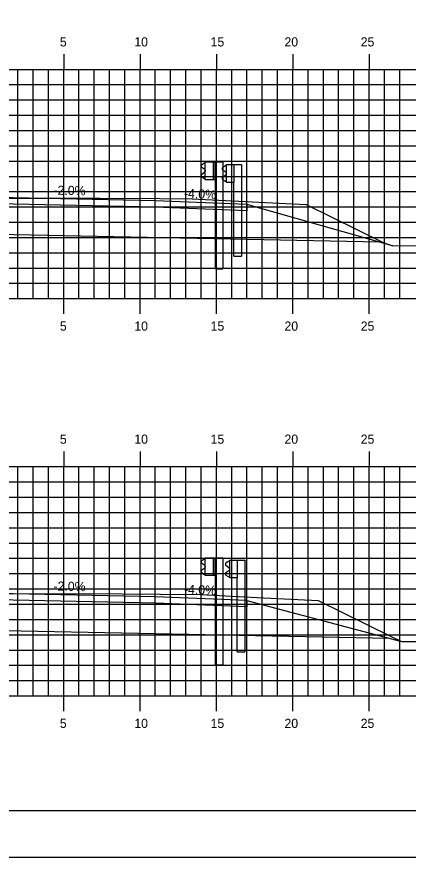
# Model space of a CAD drawing. Extents: x 2194004 to 2194525, y 863888 to 863998.
# Drawn here: x 2194256.9 to 2194282.5, y 863888.4 to 863943.4 of the extents above; entities that cross this region are included whole.
import ezdxf

# ---------------------------------------------------------------- set-up
doc = ezdxf.new("R2010")
doc.units = 0
for name, color, linetype in [('ANNOTATION', 7, 'Continuous'), ('BORDER', 7, 'Continuous'), ('D_Guardrail_Beam_Lt', 7, 'Continuous'), ('H_V ANNOTATION', 7, 'Continuous'), ('MAJOR', 7, 'Continuous'), ('MINOR', 7, 'Continuous'), ('PLOT BOUNDARY', 7, 'Continuous'), ('S_Guardrail_Beam', 7, 'Continuous'), ('S_Roadway_Centerline', 7, 'Continuous'), ('TEMPLATE', 7, 'Continuous')]:
    doc.layers.add(name, color=color, linetype=linetype)

msp = doc.modelspace()

# ---------------------------------------------------------------- linework, layer by layer
at = {"layer": 'BORDER'}
msp.add_lwpolyline([(2194179.986, 863891.446), (2194339.986, 863891.446), (2194339.986, 863996.446), (2194179.986, 863996.446)], close=True, dxfattribs=at)
at = {"layer": 'D_Guardrail_Beam_Lt'}
for p, q in [((2194269.167, 863933.788), (2194269.024, 863933.688)), ((2194269.024, 863933.545), (2194269.219, 863933.409)), ((2194269.257, 863933.809), (2194269.183, 863933.795)), ((2194269.257, 863933.892), (2194269.945, 863933.892)), ((2194269.257, 863932.726), (2194269.257, 863933.892)), ((2194269.778, 863933.892), (2194269.778, 863932.726)), ((2194269.882, 863933.892), (2194269.882, 863932.726)), ((2194269.945, 863933.892), (2194270.415, 863933.892)), ((2194269.945, 863933.892), (2194269.945, 863932.726)), ((2194270.415, 863933.892), (2194270.415, 863926.892)), ((2194269.219, 863933.21), (2194269.024, 863933.073)), ((2194269.024, 863932.93), (2194269.167, 863932.83)), ((2194269.253, 863933.344), (2194269.253, 863933.274)), ((2194269.183, 863932.824), (2194269.257, 863932.809)), ((2194269.945, 863932.726), (2194269.257, 863932.726)), ((2194269.924, 863926.892), (2194269.924, 863932.726)), ((2194269.924, 863926.892), (2194270.415, 863926.892)), ((2194269.167, 863907.878), (2194269.024, 863907.778)), ((2194269.024, 863907.635), (2194269.219, 863907.499)), ((2194269.257, 863907.899), (2194269.183, 863907.885)), ((2194269.257, 863907.982), (2194269.945, 863907.982)), ((2194269.257, 863906.816), (2194269.257, 863907.982)), ((2194269.778, 863907.982), (2194269.778, 863906.816)), ((2194269.882, 863907.982), (2194269.882, 863906.816)), ((2194269.945, 863907.982), (2194270.415, 863907.982)), ((2194269.945, 863907.982), (2194269.945, 863906.816)), ((2194270.415, 863907.982), (2194270.415, 863900.982)), ((2194269.219, 863907.3), (2194269.024, 863907.163)), ((2194269.024, 863907.02), (2194269.167, 863906.92)), ((2194269.253, 863907.434), (2194269.253, 863907.364)), ((2194269.183, 863906.914), (2194269.257, 863906.899)), ((2194269.945, 863906.816), (2194269.257, 863906.816)), ((2194269.924, 863900.982), (2194269.924, 863906.816)), ((2194269.924, 863900.982), (2194270.415, 863900.982))]:
    msp.add_line(p, q, dxfattribs=at)
for centre, major_axis, start_param, end_param in [((2194269.074, 863933.616), (-0.0877, 0), 5.323254, 7.243116), ((2194269.191, 863933.754), (-0.0417, 0), 4.907132, 5.323254), ((2194269.174, 863933.344), (0.0789, 0), 0, 0.959931), ((2194269.074, 863933.002), (-0.0877, 0), 5.323254, 7.243116), ((2194269.174, 863933.274), (0.0789, 0), 5.323254, 6.283185), ((2194269.191, 863932.864), (-0.0417, 0), 0.959931, 1.376053), ((2194269.074, 863907.706), (-0.0877, 0), 5.323254, 7.243116), ((2194269.191, 863907.844), (-0.0417, 0), 4.907132, 5.323254), ((2194269.074, 863907.092), (-0.0877, 0), 5.323254, 7.243116), ((2194269.174, 863907.434), (0.0789, 0), 0, 0.959931), ((2194269.174, 863907.364), (0.0789, 0), 5.323254, 6.283185), ((2194269.191, 863906.954), (-0.0417, 0), 0.959931, 1.376053)]:
    msp.add_ellipse(centre, major_axis=major_axis, ratio=0.995501, start_param=start_param, end_param=end_param, dxfattribs=at)
at = {"layer": 'MAJOR'}
for p, q in [((2194259.986, 863940.948), (2194259.986, 863939.946)), ((2194264.986, 863940.948), (2194264.986, 863939.946)), ((2194269.986, 863940.948), (2194269.986, 863939.946)), ((2194274.986, 863940.948), (2194274.986, 863939.946)), ((2194279.986, 863940.948), (2194279.986, 863939.946)), ((2194184.986, 863939.946), (2194324.986, 863939.946)), ((2194184.986, 863939.946), (2194324.986, 863939.946)), ((2194259.986, 863924.946), (2194259.986, 863939.946)), ((2194264.986, 863924.946), (2194264.986, 863939.946)), ((2194269.986, 863924.946), (2194269.986, 863939.946)), ((2194274.986, 863924.946), (2194274.986, 863939.946)), ((2194279.986, 863924.946), (2194279.986, 863939.946)), ((2194184.986, 863934.946), (2194324.986, 863934.946)), ((2194184.986, 863929.946), (2194324.986, 863929.946)), ((2194184.986, 863924.946), (2194324.986, 863924.946)), ((2194259.986, 863923.944), (2194259.986, 863924.946)), ((2194264.986, 863923.944), (2194264.986, 863924.946)), ((2194269.986, 863923.944), (2194269.986, 863924.946)), ((2194274.986, 863923.944), (2194274.986, 863924.946)), ((2194279.986, 863923.944), (2194279.986, 863924.946)), ((2194259.986, 863914.948), (2194259.986, 863913.946)), ((2194264.986, 863914.948), (2194264.986, 863913.946)), ((2194269.986, 863914.948), (2194269.986, 863913.946)), ((2194274.986, 863914.948), (2194274.986, 863913.946)), ((2194279.986, 863914.948), (2194279.986, 863913.946)), ((2194184.986, 863913.946), (2194324.986, 863913.946)), ((2194184.986, 863913.946), (2194324.986, 863913.946)), ((2194259.986, 863898.946), (2194259.986, 863913.946)), ((2194264.986, 863898.946), (2194264.986, 863913.946)), ((2194269.986, 863898.946), (2194269.986, 863913.946)), ((2194274.986, 863898.946), (2194274.986, 863913.946)), ((2194279.986, 863898.946), (2194279.986, 863913.946)), ((2194184.986, 863908.946), (2194324.986, 863908.946)), ((2194184.986, 863903.946), (2194324.986, 863903.946)), ((2194184.986, 863898.946), (2194324.986, 863898.946)), ((2194259.986, 863897.944), (2194259.986, 863898.946)), ((2194264.986, 863897.944), (2194264.986, 863898.946)), ((2194269.986, 863897.944), (2194269.986, 863898.946)), ((2194274.986, 863897.944), (2194274.986, 863898.946)), ((2194279.986, 863897.944), (2194279.986, 863898.946))]:
    msp.add_line(p, q, dxfattribs=at)
at = {"layer": 'MINOR'}
for p, q in [((2194256.986, 863924.946), (2194256.986, 863939.946)), ((2194257.986, 863924.946), (2194257.986, 863939.946)), ((2194258.986, 863924.946), (2194258.986, 863939.946)), ((2194260.986, 863924.946), (2194260.986, 863939.946)), ((2194261.986, 863924.946), (2194261.986, 863939.946)), ((2194262.986, 863924.946), (2194262.986, 863939.946)), ((2194263.986, 863924.946), (2194263.986, 863939.946)), ((2194265.986, 863924.946), (2194265.986, 863939.946)), ((2194266.986, 863924.946), (2194266.986, 863939.946)), ((2194267.986, 863924.946), (2194267.986, 863939.946)), ((2194268.986, 863924.946), (2194268.986, 863939.946)), ((2194270.986, 863924.946), (2194270.986, 863939.946)), ((2194271.986, 863924.946), (2194271.986, 863939.946)), ((2194272.986, 863924.946), (2194272.986, 863939.946)), ((2194273.986, 863924.946), (2194273.986, 863939.946)), ((2194275.986, 863924.946), (2194275.986, 863939.946)), ((2194276.986, 863924.946), (2194276.986, 863939.946)), ((2194277.986, 863924.946), (2194277.986, 863939.946)), ((2194278.986, 863924.946), (2194278.986, 863939.946)), ((2194280.986, 863924.946), (2194280.986, 863939.946)), ((2194281.986, 863924.946), (2194281.986, 863939.946)), ((2194184.986, 863938.946), (2194324.986, 863938.946)), ((2194184.986, 863937.946), (2194324.986, 863937.946)), ((2194184.986, 863936.946), (2194324.986, 863936.946)), ((2194184.986, 863935.946), (2194324.986, 863935.946)), ((2194184.986, 863933.946), (2194324.986, 863933.946)), ((2194184.986, 863932.946), (2194324.986, 863932.946)), ((2194184.986, 863931.946), (2194324.986, 863931.946)), ((2194184.986, 863930.946), (2194324.986, 863930.946)), ((2194184.986, 863928.946), (2194324.986, 863928.946)), ((2194184.986, 863927.946), (2194324.986, 863927.946)), ((2194184.986, 863926.946), (2194324.986, 863926.946)), ((2194184.986, 863925.946), (2194324.986, 863925.946)), ((2194256.986, 863898.946), (2194256.986, 863913.946)), ((2194257.986, 863898.946), (2194257.986, 863913.946)), ((2194258.986, 863898.946), (2194258.986, 863913.946)), ((2194260.986, 863898.946), (2194260.986, 863913.946)), ((2194261.986, 863898.946), (2194261.986, 863913.946)), ((2194262.986, 863898.946), (2194262.986, 863913.946)), ((2194263.986, 863898.946), (2194263.986, 863913.946)), ((2194265.986, 863898.946), (2194265.986, 863913.946)), ((2194266.986, 863898.946), (2194266.986, 863913.946)), ((2194267.986, 863898.946), (2194267.986, 863913.946)), ((2194268.986, 863898.946), (2194268.986, 863913.946)), ((2194270.986, 863898.946), (2194270.986, 863913.946)), ((2194271.986, 863898.946), (2194271.986, 863913.946)), ((2194272.986, 863898.946), (2194272.986, 863913.946)), ((2194273.986, 863898.946), (2194273.986, 863913.946)), ((2194275.986, 863898.946), (2194275.986, 863913.946)), ((2194276.986, 863898.946), (2194276.986, 863913.946)), ((2194277.986, 863898.946), (2194277.986, 863913.946)), ((2194278.986, 863898.946), (2194278.986, 863913.946)), ((2194280.986, 863898.946), (2194280.986, 863913.946)), ((2194281.986, 863898.946), (2194281.986, 863913.946)), ((2194184.986, 863912.946), (2194324.986, 863912.946)), ((2194184.986, 863911.946), (2194324.986, 863911.946)), ((2194184.986, 863910.946), (2194324.986, 863910.946)), ((2194184.986, 863909.946), (2194324.986, 863909.946)), ((2194184.986, 863907.946), (2194324.986, 863907.946)), ((2194184.986, 863906.946), (2194324.986, 863906.946)), ((2194184.986, 863905.946), (2194324.986, 863905.946)), ((2194184.986, 863904.946), (2194324.986, 863904.946)), ((2194184.986, 863902.946), (2194324.986, 863902.946)), ((2194184.986, 863901.946), (2194324.986, 863901.946)), ((2194184.986, 863900.946), (2194324.986, 863900.946)), ((2194184.986, 863899.946), (2194324.986, 863899.946))]:
    msp.add_line(p, q, dxfattribs=at)
at = {"layer": 'PLOT BOUNDARY'}
msp.add_lwpolyline([(2194171.893, 863888.387), (2194341.893, 863888.387), (2194341.893, 863998.387), (2194171.893, 863998.387)], close=True, dxfattribs=at)
at = {"layer": 'S_Guardrail_Beam'}
for p, q in [((2194270.539, 863933.621), (2194270.396, 863933.521)), ((2194270.638, 863933.643), (2194270.556, 863933.628)), ((2194270.638, 863933.716), (2194271.127, 863933.716)), ((2194270.638, 863932.549), (2194270.638, 863933.716)), ((2194271.127, 863933.716), (2194271.619, 863933.716)), ((2194271.127, 863933.716), (2194271.127, 863932.549)), ((2194271.619, 863933.716), (2194271.619, 863927.716)), ((2194270.396, 863933.378), (2194270.591, 863933.242)), ((2194270.591, 863933.022), (2194270.396, 863932.886)), ((2194270.625, 863933.178), (2194270.625, 863933.087)), ((2194270.396, 863932.743), (2194270.539, 863932.643)), ((2194270.556, 863932.636), (2194270.638, 863932.622)), ((2194271.127, 863932.549), (2194270.638, 863932.549)), ((2194271.127, 863927.716), (2194271.127, 863932.549)), ((2194271.127, 863927.716), (2194271.619, 863927.716)), ((2194270.756, 863907.733), (2194270.612, 863907.633)), ((2194270.854, 863907.754), (2194270.772, 863907.74)), ((2194270.854, 863907.827), (2194271.344, 863907.827)), ((2194270.854, 863906.661), (2194270.854, 863907.827)), ((2194271.344, 863907.827), (2194271.836, 863907.827)), ((2194271.344, 863907.827), (2194271.344, 863906.661)), ((2194271.836, 863907.827), (2194271.836, 863901.827)), ((2194270.612, 863907.49), (2194270.808, 863907.354)), ((2194270.808, 863907.134), (2194270.612, 863906.998)), ((2194270.841, 863907.289), (2194270.841, 863907.198)), ((2194270.612, 863906.855), (2194270.756, 863906.755)), ((2194270.772, 863906.748), (2194270.854, 863906.733)), ((2194271.344, 863906.661), (2194270.854, 863906.661)), ((2194271.344, 863901.827), (2194271.344, 863906.661)), ((2194271.344, 863901.827), (2194271.836, 863901.827))]:
    msp.add_line(p, q, dxfattribs=at)
for centre, major_axis, start_param, end_param in [((2194270.446, 863933.45), (-0.0877, 0), 5.323254, 7.243116), ((2194270.563, 863933.587), (-0.0417, 0), 4.886922, 5.323254), ((2194270.446, 863932.815), (-0.0877, 0), 5.323254, 7.243116), ((2194270.546, 863933.178), (0.0789, 0), 0, 0.959931), ((2194270.546, 863933.087), (0.0789, 0), 5.323254, 6.283185), ((2194270.563, 863932.677), (-0.0417, 0), 0.959931, 1.396263), ((2194270.662, 863907.561), (-0.0877, 0), 5.323254, 7.243116), ((2194270.78, 863907.699), (-0.0417, 0), 4.886922, 5.323254), ((2194270.762, 863907.289), (0.0789, 0), 0, 0.959931), ((2194270.762, 863907.198), (0.0789, 0), 5.323254, 6.283185), ((2194270.662, 863906.926), (-0.0877, 0), 5.323254, 7.243116), ((2194270.78, 863906.789), (-0.0417, 0), 0.959931, 1.396263)]:
    msp.add_ellipse(centre, major_axis=major_axis, ratio=0.995501, start_param=start_param, end_param=end_param, dxfattribs=at)
at = {"layer": 'S_Roadway_Centerline'}
for points in [[(2194184.986, 863925.019), (2194197.636, 863925.346), (2194206.425, 863925.541), (2194218.588, 863925.816), (2194219.347, 863925.914), (2194232.657, 863930.448), (2194232.831, 863930.509), (2194232.96, 863930.521), (2194238.587, 863931.16), (2194241.156, 863931.241), (2194243.336, 863931.371), (2194250.982, 863931.437), (2194254.953, 863931.509), (2194262.373, 863931.527), (2194266.278, 863931.497), (2194268.391, 863931.477), (2194272.752, 863931.249), (2194275.855, 863931.097), (2194280.904, 863928.615), (2194281.523, 863928.402), (2194284.108, 863928.415)], [(2194184.986, 863899.44), (2194193.736, 863899.667), (2194220.459, 863900.26), (2194220.779, 863900.267), (2194220.835, 863900.267), (2194220.887, 863900.279), (2194220.888, 863900.279), (2194233.802, 863904.693), (2194234.003, 863904.728), (2194238.543, 863905.244), (2194240.565, 863905.308), (2194243.32, 863905.472), (2194249.921, 863905.529), (2194254.949, 863905.619), (2194261.358, 863905.635), (2194266.294, 863905.597), (2194268.965, 863905.572), (2194272.648, 863905.379), (2194276.655, 863905.184), (2194281.436, 863902.833), (2194282.094, 863902.5), (2194284.53, 863902.509)]]:
    msp.add_lwpolyline(points, dxfattribs=at)
at = {"layer": 'TEMPLATE'}
for p, q in [((2194265.986, 863931.346), (2194254.986, 863931.566)), ((2194271.986, 863931.106), (2194265.986, 863931.346)), ((2194265.986, 863930.929), (2194254.986, 863931.149)), ((2194281.523, 863928.402), (2194271.986, 863931.106)), ((2194280.701, 863928.635), (2194254.986, 863929.149)), ((2194265.986, 863905.436), (2194254.986, 863905.656)), ((2194271.986, 863905.196), (2194265.986, 863905.436)), ((2194265.986, 863905.019), (2194254.986, 863905.239)), ((2194271.986, 863905.196), (2194282.094, 863902.5))]:
    msp.add_line(p, q, dxfattribs=at)
for points in [[(2194271.986, 863931.106), (2194271.986, 863930.689), (2194265.986, 863930.929)], [(2194271.986, 863904.779), (2194271.986, 863905.196), (2194271.986, 863904.779), (2194265.986, 863905.019)], [(2194224.797, 863902.635), (2194243.986, 863903.019), (2194254.986, 863903.239), (2194265.986, 863903.019), (2194281.297, 863902.713)]]:
    msp.add_lwpolyline(points, dxfattribs=at)

# ---------------------------------------------------------------- texts
at = {"layer": 'ANNOTATION'}
for s, rotation, p in [('-2.0%', 358.8542, (2194259.315, 863931.746)), ('-4.0%', 357.7094, (2194267.853, 863931.538)), ('-2.0%', 358.8542, (2194259.315, 863905.836)), ('-4.0%', 357.7094, (2194267.853, 863905.628))]:
    msp.add_text(s, height=0.6, rotation=rotation, dxfattribs=at).set_placement(p)
at = {"layer": 'H_V ANNOTATION'}
for s, p in [('5', (2194259.737, 863941.446)), ('10', (2194264.612, 863941.446)), ('15', (2194269.604, 863941.446)), ('20', (2194274.44, 863941.446)), ('25', (2194279.432, 863941.446)), ('5', (2194259.737, 863922.846)), ('10', (2194264.612, 863922.846)), ('15', (2194269.604, 863922.846)), ('20', (2194274.44, 863922.846)), ('25', (2194279.432, 863922.846)), ('5', (2194259.737, 863915.446)), ('10', (2194264.612, 863915.446)), ('15', (2194269.604, 863915.446)), ('20', (2194274.44, 863915.446)), ('25', (2194279.432, 863915.446)), ('5', (2194259.737, 863896.846)), ('10', (2194264.612, 863896.846)), ('15', (2194269.604, 863896.846)), ('20', (2194274.44, 863896.846)), ('25', (2194279.432, 863896.846))]:
    msp.add_text(s, height=0.6, dxfattribs=at).set_placement(p)

doc.saveas('drawing.dxf')
